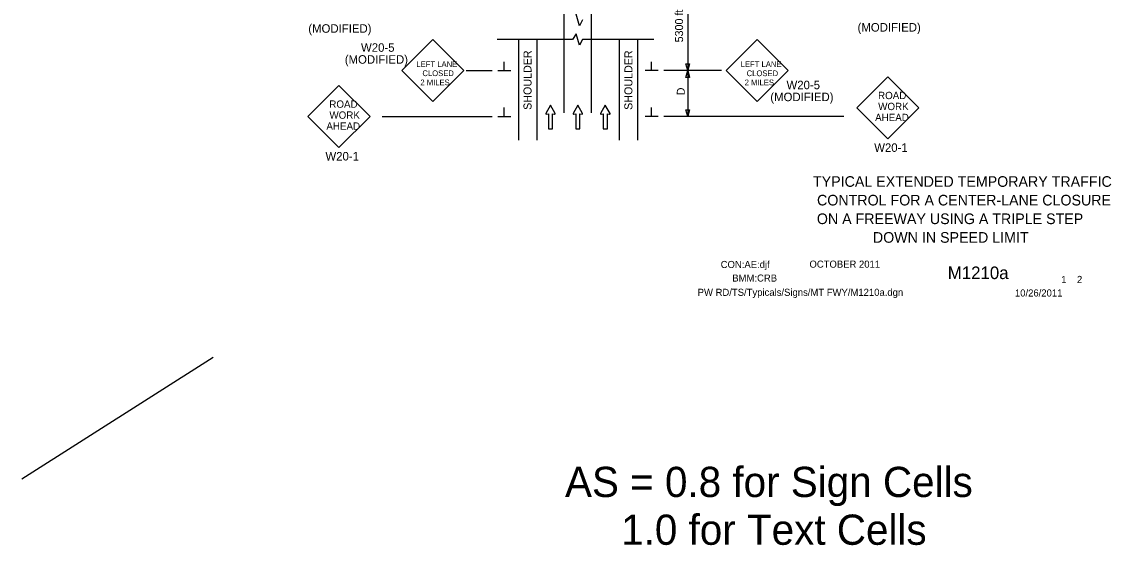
# Model space of a CAD drawing. Extents: x 16480 to 18482, y 7002 to 8333.
# Drawn here: x 16480 to 17432, y 7002 to 7460 of the extents above; entities that cross this region are included whole.
import ezdxf

# ---------------------------------------------------------------- set-up
doc = ezdxf.new("R2010")
doc.units = 0
for name, color, linetype in [('ALI_LEGAL_EX', 7, 'Continuous'), ('BORDER', 7, 'Continuous'), ('BORDER_SIGNAL_WO', 7, 'Continuous'), ('MT_SCRATCH_LEVEL_E', 7, 'Continuous'), ('PAVT_EDGE_EX', 7, 'Continuous'), ('TRAFFIC_SIGNS_PR', 7, 'Continuous'), ('TYPICAL_TEXT_DIMEN_PR', 7, 'Continuous')]:
    doc.layers.add(name, color=color, linetype=linetype)

msp = doc.modelspace()

# ---------------------------------------------------------------- linework, layer by layer
at = {"layer": 'ALI_LEGAL_EX'}
for p, q in [((16953.87, 7379.99), (16953.87, 7560.8)), ((16977.87, 7379.99), (16977.87, 7560.8))]:
    msp.add_line(p, q, dxfattribs=at)
for points in [[(16953.87, 7380.93), (16953.87, 7405.93)], [(16977.87, 7380.93), (16977.87, 7405.93)]]:
    msp.add_lwpolyline(points, dxfattribs=at)
at = {"layer": 'MT_SCRATCH_LEVEL_E'}
for p, q in [((16941.87, 7386.81), (16937.75, 7379.57)), ((16946.01, 7379.57), (16941.87, 7386.81)), ((16965.77, 7386.81), (16961.66, 7379.57)), ((16969.92, 7379.57), (16965.77, 7386.81)), ((16989.82, 7386.81), (16985.71, 7379.57)), ((16993.97, 7379.57), (16989.82, 7386.81)), ((16938.24, 7378.88), (16940.01, 7379.2)), ((16940.01, 7379.2), (16940.01, 7365.94)), ((16943.76, 7365.94), (16943.76, 7379.2)), ((16943.76, 7379.2), (16945.53, 7378.88)), ((16962.14, 7378.88), (16963.92, 7379.2)), ((16963.92, 7379.2), (16963.92, 7365.94)), ((16967.66, 7365.94), (16967.66, 7379.2)), ((16967.66, 7379.2), (16969.44, 7378.88)), ((16986.19, 7378.88), (16987.97, 7379.2)), ((16987.97, 7379.2), (16987.97, 7365.94)), ((16991.71, 7365.94), (16991.71, 7379.2)), ((16991.71, 7379.2), (16993.49, 7378.88)), ((16940.01, 7365.94), (16943.76, 7365.94)), ((16963.92, 7365.94), (16967.66, 7365.94)), ((16987.97, 7365.94), (16991.71, 7365.94))]:
    msp.add_line(p, q, dxfattribs=at)
for centre, start, end in [((16938.16, 7379.34), 150.42484, 279.96381), ((16945.6, 7379.34), 260.03619, 29.77312), ((16962.07, 7379.34), 150.42484, 279.96381), ((16969.51, 7379.34), 260.03619, 29.77312), ((16986.12, 7379.34), 150.42484, 279.96381), ((16993.56, 7379.34), 260.03619, 29.77312)]:
    msp.add_arc(centre, 0.463, start, end, dxfattribs=at)
at = {"layer": 'PAVT_EDGE_EX'}
for p, q in [((16913.87, 7444.25), (16913.87, 7356.17)), ((16929.87, 7444.25), (16929.87, 7356.17)), ((17001.87, 7444.25), (17001.87, 7356.17)), ((17017.87, 7444.25), (17017.87, 7356.17))]:
    msp.add_line(p, q, dxfattribs=at)
at = {"layer": 'TRAFFIC_SIGNS_PR'}
for p, q in [((16839.06, 7444.15), (16811.9, 7416.99)), ((16866.21, 7416.99), (16839.06, 7444.15)), ((17122.55, 7444.1), (17095.39, 7416.95)), ((17149.7, 7416.95), (17122.55, 7444.1)), ((16811.9, 7416.99), (16839.06, 7389.84)), ((16839.06, 7389.84), (16866.21, 7416.99)), ((17095.39, 7416.95), (17122.55, 7389.8)), ((17122.55, 7389.8), (17149.7, 7416.95)), ((17236.72, 7411.64), (17209.56, 7384.48)), ((17263.87, 7384.48), (17236.72, 7411.64)), ((16756.97, 7404.08), (16729.82, 7376.93)), ((16784.12, 7376.93), (16756.97, 7404.08)), ((17209.56, 7384.48), (17236.72, 7357.33)), ((17236.72, 7357.33), (17263.87, 7384.48)), ((16729.82, 7376.93), (16756.97, 7349.78)), ((16756.97, 7349.78), (16784.12, 7376.93))]:
    msp.add_line(p, q, dxfattribs=at)
at = {"layer": 'TYPICAL_TEXT_DIMEN_PR'}
for p, q in [((17061.87, 7498.5), (17061.87, 7416.94)), ((16967.21, 7456.25), (16964.47, 7466.19)), ((16969.95, 7461.39), (16967.21, 7456.25)), ((16964.47, 7449.05), (16961.21, 7444.25)), ((16967.21, 7439.11), (16964.47, 7449.05)), ((16961.21, 7444.25), (16895.27, 7444.25)), ((16969.95, 7444.25), (16967.21, 7439.11)), ((17032.29, 7444.25), (16969.95, 7444.25)), ((16901.49, 7416.94), (16901.49, 7424.72)), ((17030.24, 7416.94), (17030.24, 7424.72)), ((17061.87, 7416.94), (17060.3, 7422.8)), ((17060.3, 7422.8), (17061.87, 7422.8)), ((17061.87, 7422.8), (17063.44, 7422.8)), ((17063.44, 7422.8), (17061.87, 7416.94)), ((16868.18, 7416.94), (16890.87, 7416.94)), ((16895.87, 7416.94), (16907.12, 7416.94)), ((17035.87, 7416.94), (17024.62, 7416.94)), ((17091.49, 7416.94), (17040.87, 7416.94)), ((17060.3, 7411.07), (17061.87, 7416.94)), ((17061.87, 7411.07), (17060.3, 7411.07)), ((17061.87, 7416.94), (17061.87, 7376.94)), ((17061.87, 7416.94), (17063.44, 7411.07)), ((17063.44, 7411.07), (17061.87, 7411.07)), ((16901.49, 7376.94), (16901.49, 7384.72)), ((17030.24, 7376.94), (17030.24, 7384.72)), ((17061.87, 7376.94), (17060.3, 7382.8)), ((17060.3, 7382.8), (17061.87, 7382.8)), ((17061.87, 7382.8), (17063.44, 7382.8)), ((17063.44, 7382.8), (17061.87, 7376.94)), ((16794.77, 7376.94), (16890.87, 7376.94)), ((16895.87, 7376.94), (16907.12, 7376.94)), ((17035.87, 7376.94), (17024.62, 7376.94)), ((17198.2, 7376.94), (17040.87, 7376.94)), ((16647.08, 7166.01), (16479.65, 7059.76))]:
    msp.add_line(p, q, dxfattribs=at)

# ---------------------------------------------------------------- texts
at = {"layer": 'BORDER'}
for s, p in [('TYPICAL EXTENDED TEMPORARY TRAFFIC', (17171.38, 7315.31)), ('CONTROL FOR A CENTER-LANE CLOSURE', (17174.9, 7299.01)), ('ON A FREEWAY USING A TRIPLE STEP ', (17174.75, 7282.71)), ('DOWN IN SPEED LIMIT', (17223.75, 7266.41))]:
    msp.add_text(s, height=9.3, dxfattribs=at).set_placement(p)
at = {"layer": 'BORDER_SIGNAL_WO'}
for s, height, p in [('CON:AE:djf  ', 6.2, (17090.69, 7244.31)), ('    OCTOBER 2011    ', 6.2, (17159.08, 7244.59)), ('BMM:CRB   ', 6.2, (17100.81, 7232.42)), ('    M1210a   ', 11, (17272.86, 7234.63)), (' 1    2 ', 6.2, (17386.06, 7231.2)), ('PW RD/TS/Typicals/Signs/MT FWY/M1210a.dgn      ', 6.2, (17070.55, 7219.96)), ('10/26/2011    ', 6.2, (17347.93, 7219.38)), ('AS = 0.8 for Sign Cells', 26.4241, (16954.57, 7044.01)), ('     1.0 for Text Cells', 26.4241, (16954.57, 7002.22))]:
    msp.add_text(s, height=height, dxfattribs=at).set_placement(p)
at = {"layer": 'TRAFFIC_SIGNS_PR'}
for s, height, p in [('(MODIFIED)', 7.44, (16730.13, 7450.08)), ('(MODIFIED)', 7.44, (17210.35, 7451.1)), ('W20-5', 7.44, (16776.21, 7433.43)), ('(MODIFIED)', 7.44, (16762.03, 7422.99)), ('LEFT LANE', 5, (16824.68, 7420.15)), ('LEFT LANE', 5, (17108.18, 7420.11)), ('CLOSED', 5, (16829.89, 7412.15)), ('CLOSED', 5, (17113.38, 7412.11)), ('2 MILES', 5, (16828.14, 7404.15)), ('2 MILES', 5, (17111.63, 7404.11)), ('W20-5', 7.44, (17148.24, 7400.68)), ('(MODIFIED)', 7.44, (17134.06, 7390.24)), ('ROAD', 6.4, (17228.26, 7392.02)), ('ROAD', 6.4, (16748.51, 7384.47)), ('WORK', 6.4, (17228.37, 7382.42)), ('WORK', 6.4, (16748.62, 7374.87)), ('AHEAD', 6.4, (17225.68, 7372.82)), ('AHEAD', 6.4, (16745.93, 7365.27)), ('W20-1', 7.44, (17224.89, 7345.89)), ('W20-1', 7.44, (16745.14, 7338.34))]:
    msp.add_text(s, height=height, dxfattribs=at).set_placement(p)
at = {"layer": 'TYPICAL_TEXT_DIMEN_PR'}
for s, p in [('5300 ft', (17057.78, 7441.66)), ('SHOULDER', (16925.29, 7382.65)), ('SHOULDER', (17013.49, 7382.65)), ('D', (17059.31, 7395.36))]:
    msp.add_text(s, height=7, rotation=90, dxfattribs=at).set_placement(p)

doc.saveas('drawing.dxf')
